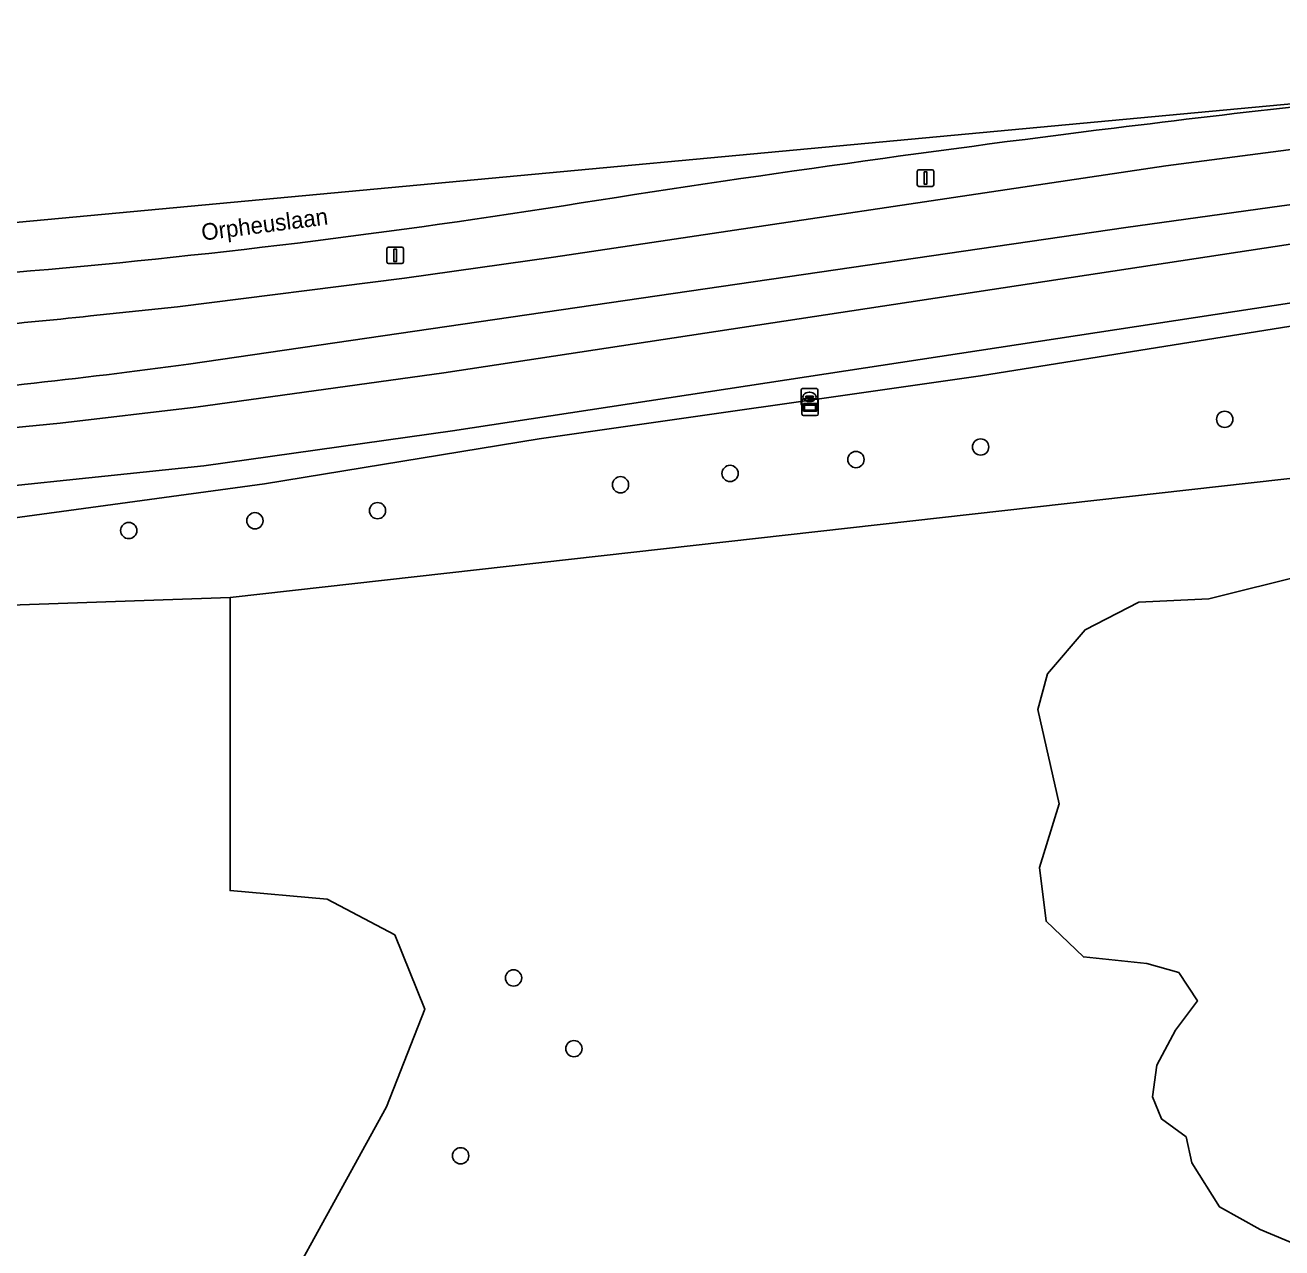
# Model space of a CAD drawing. Extents: x 161758 to 162722, y 384793 to 385405.
# Drawn here: x 162584.7 to 162660.3, y 385330.2 to 385403.7 of the extents above; entities that cross this region are included whole.
import ezdxf

# ---------------------------------------------------------------- set-up
doc = ezdxf.new("R2010")
doc.units = 0
for name, color, linetype in [('IMGEO_Berm_groen', 7, 'Continuous'), ('IMGEO_Boom', 7, 'Continuous'), ('IMGEO_Brandkraan', 7, 'Continuous'), ('IMGEO_Fietspad_gesloten', 7, 'Continuous'), ('IMGEO_Greppel_droge_sloot', 7, 'Continuous'), ('IMGEO_Groenvoorziening', 7, 'Continuous'), ('IMGEO_Lichtmast', 7, 'Continuous'), ('IMGEO_Loofbos', 7, 'Continuous'), ('IMGEO_Moeras', 7, 'Continuous'), ('IMGEO_Openbare_ruimte_label', 7, 'Continuous'), ('IMGEO_Rietland', 7, 'Continuous'), ('IMGEO_Rijbaan_lokaal_gesloten', 7, 'Continuous'), ('IMGEO_Verklikker', 7, 'Continuous')]:
    doc.layers.add(name, color=color, linetype=linetype)

msp = doc.modelspace()

# ---------------------------------------------------------------- linework, layer by layer
at = {"layer": 'IMGEO_Berm_groen'}
for points in [[(162660.257, 385392.853), (162650.874, 385391.567), (162594.54, 385383.334)], [(162576.692, 385378.812), (162586.817, 385379.801), (162594.968, 385380.749), (162609.882, 385382.816), (162660.767, 385390.553)]]:
    msp.add_lwpolyline(points, dxfattribs=at)
for centre, radius, start, end in [((162736.202, 384879.222), 519.215, 95.72988, 98.41074), ((162534.96, 385832.512), 453.112, 275.03456, 277.55569)]:
    msp.add_arc(centre, radius, start, end, dxfattribs=at)
at = {"layer": 'IMGEO_Boom'}
for centre in [(162656.822, 385380.027), (162642.149, 385378.364), (162634.653, 385377.609), (162627.089, 385376.773), (162620.501, 385376.091), (162605.894, 385374.536), (162590.941, 385373.343), (162598.524, 385373.928), (162614.071, 385346.448), (162617.699, 385342.198), (162610.889, 385335.757)]:
    msp.add_circle(centre, 0.489, dxfattribs=at)
at = {"layer": 'IMGEO_Brandkraan'}
for p, q in [((162631.361, 385380.945), (162631.361, 385381.797)), ((162631.436, 385381.871), (162632.288, 385381.871)), ((162631.62, 385381.365), (162631.62, 385381.377)), ((162632.058, 385381.328), (162631.66, 385381.328)), ((162631.663, 385381.414), (162632.061, 385381.414)), ((162631.849, 385381.651), (162631.874, 385381.651)), ((162632.104, 385381.377), (162632.104, 385381.365)), ((162632.362, 385381.797), (162632.362, 385380.945)), ((162632.288, 385380.871), (162631.436, 385380.871)), ((162631.872, 385381.091), (162631.847, 385381.091))]:
    msp.add_line(p, q, dxfattribs=at)
for points in [[(162631.361, 385380.945), (162631.361, 385381.797)], [(162631.436, 385381.871), (162632.288, 385381.871)], [(162632.362, 385381.797), (162632.362, 385380.945)], [(162632.288, 385380.871), (162631.436, 385380.871)]]:
    msp.add_lwpolyline(points, dxfattribs=at)
for centre, radius, start, end in [((162631.438, 385381.795), 0.0765, 91.55205, 178.44795), ((162631.438, 385381.795), 0.0765, 91.55205, 178.44795), ((162631.66, 385381.374), 0.0403, 85.87752, 175.75265), ((162631.657, 385381.364), 0.0366, 178.93798, 274.71019), ((162632.061, 385381.371), 0.043, 264.86636, 352.45326), ((162632.065, 385381.376), 0.0386, 1.73085, 96.63898), ((162632.286, 385381.795), 0.0765, 1.55205, 88.44795), ((162632.286, 385381.795), 0.0765, 1.55205, 88.44795), ((162631.438, 385380.947), 0.0765, 181.55205, 268.44795), ((162631.438, 385380.947), 0.0765, 181.55205, 268.44795), ((162632.286, 385380.947), 0.0765, 271.55205, 358.44795), ((162632.286, 385380.947), 0.0765, 271.55205, 358.44795)]:
    msp.add_arc(centre, radius, start, end, dxfattribs=at)
for centre, major_axis, ratio, start_param, end_param in [((162631.848, 385381.371), (-0.387, 0.002), 0.722429, 4.712389, 7.853982), ((162631.873, 385381.371), (-0.39, 0.002), 0.717154, 1.570796, 4.712389)]:
    msp.add_ellipse(centre, major_axis=major_axis, ratio=ratio, start_param=start_param, end_param=end_param, dxfattribs=at)
at = {"layer": 'IMGEO_Fietspad_gesloten'}
for points in [[(162677.197, 385393.316), (162660.767, 385390.553), (162609.882, 385382.816), (162594.968, 385380.749), (162586.817, 385379.801), (162576.692, 385378.812)], [(162576.625, 385375.27), (162595.45, 385377.228), (162610.41, 385379.329), (162660.98, 385387.042)]]:
    msp.add_lwpolyline(points, dxfattribs=at)
at = {"layer": 'IMGEO_Greppel_droge_sloot'}
msp.add_lwpolyline([(162588.634, 385386.239), (162593.869, 385386.792), (162607.514, 385388.514), (162616.475, 385389.77), (162653.281, 385395.256), (162662.034, 385396.405), (162671.163, 385397.596), (162683.886, 385399.101), (162688.344, 385399.628), (162699.463, 385400.722), (162707.521, 385401.494), (162711.775, 385401.902), (162711.608, 385403.721), (162673.311, 385400.161)], dxfattribs=at)
for centre, radius, start, end in [((162801.259, 384169.618), 1237.176, 95.936109, 97.014727), ((162773.539, 384402.583), 1002.57, 97.068339, 99.040149), ((162545.105, 385847.699), 460.49, 274.5738, 278.85735), ((162547.837, 385772.297), 388.208, 273.93158, 276.03232)]:
    msp.add_arc(centre, radius, start, end, dxfattribs=at)
at = {"layer": 'IMGEO_Groenvoorziening'}
for points in [[(162527.404, 385371.37), (162527.321, 385371.34), (162527.238, 385371.311), (162526.098, 385370.364), (162527.997, 385366.92), (162539.753, 385367.326), (162547.529, 385371.515), (162564.34, 385372.34), (162582.172, 385373.835), (162599.09, 385376.156), (162615.602, 385378.857), (162642.131, 385382.641), (162662.807, 385385.945), (162675.8, 385387.511), (162689.997, 385389.07), (162700.369, 385389.783), (162701.701, 385389.875)], [(162677.702, 385389.81), (162660.98, 385387.042), (162610.41, 385379.329), (162595.45, 385377.228), (162576.625, 385375.27)]]:
    msp.add_lwpolyline(points, dxfattribs=at)
at = {"layer": 'IMGEO_Lichtmast'}
for p, q in [((162638.337, 385394.131), (162638.337, 385394.931)), ((162638.337, 385394.931), (162638.337, 385394.131)), ((162638.437, 385395.031), (162639.227, 385395.031)), ((162639.227, 385395.031), (162638.437, 385395.031)), ((162639.327, 385394.931), (162639.327, 385394.131)), ((162639.327, 385394.131), (162639.327, 385394.931)), ((162639.227, 385394.031), (162638.437, 385394.031)), ((162638.437, 385394.031), (162639.227, 385394.031)), ((162606.556, 385390.384), (162607.346, 385390.384)), ((162607.346, 385390.384), (162606.556, 385390.384)), ((162606.456, 385389.484), (162606.456, 385390.284)), ((162606.456, 385390.284), (162606.456, 385389.484)), ((162607.446, 385390.284), (162607.446, 385389.484)), ((162607.446, 385389.484), (162607.446, 385390.284)), ((162607.346, 385389.384), (162606.556, 385389.384)), ((162606.556, 385389.384), (162607.346, 385389.384))]:
    msp.add_line(p, q, dxfattribs=at)
for points in [[(162638.757, 385394.906), (162638.907, 385394.906), (162638.907, 385394.156), (162638.757, 385394.156), (162638.757, 385394.906)], [(162606.876, 385390.259), (162607.026, 385390.259), (162607.026, 385389.509), (162606.876, 385389.509), (162606.876, 385390.259)]]:
    msp.add_lwpolyline(points, dxfattribs=at)
for centre, start, end in [((162638.437, 385394.931), 90, 180), ((162638.437, 385394.931), 90, 180), ((162639.227, 385394.931), 0, 90), ((162639.227, 385394.931), 360, 90), ((162638.437, 385394.131), 180, 270), ((162638.437, 385394.131), 180, 270), ((162639.227, 385394.131), 270, 0), ((162639.227, 385394.131), 270, 0), ((162606.556, 385390.284), 90, 180), ((162606.556, 385390.284), 90, 180), ((162607.346, 385390.284), 0, 90), ((162607.346, 385390.284), 360, 90), ((162606.556, 385389.484), 180, 270), ((162606.556, 385389.484), 180, 270), ((162607.346, 385389.484), 270, 0), ((162607.346, 385389.484), 270, 0)]:
    msp.add_arc(centre, 0.1, start, end, dxfattribs=at)
at = {"layer": 'IMGEO_Loofbos'}
msp.add_lwpolyline([(162663.808, 385382.469), (162662.807, 385385.945), (162642.131, 385382.641), (162615.602, 385378.857), (162599.09, 385376.156), (162582.172, 385373.835), (162564.34, 385372.34), (162547.529, 385371.515), (162539.753, 385367.326), (162563.714, 385368.155), (162597.028, 385369.308), (162671.437, 385377.676), (162671.166, 385383.084)], close=True, dxfattribs=at)
msp.add_lwpolyline([(162661.736, 385370.702), (162655.865, 385369.235), (162651.657, 385369.039), (162648.428, 385367.375), (162646.178, 385364.734), (162645.591, 385362.581), (162646.863, 385356.906), (162645.689, 385353.09), (162646.08, 385349.861), (162648.33, 385347.708), (162652.147, 385347.317), (162654.055, 385346.779), (162655.18, 385345.066), (162653.859, 385343.305), (162652.734, 385341.201), (162652.489, 385339.293), (162653.027, 385337.972), (162654.495, 385336.896), (162654.837, 385335.33), (162656.501, 385332.689), (162658.947, 385331.319), (162661.295, 385330.34)], dxfattribs=at)
at = {"layer": 'IMGEO_Moeras'}
for points in [[(162671.437, 385377.676), (162597.028, 385369.308), (162597.028, 385351.698), (162602.865, 385351.193), (162606.928, 385349.037), (162608.739, 385344.579), (162606.439, 385338.699), (162597.031, 385321.639)], [(162661.295, 385330.34), (162658.947, 385331.319), (162656.501, 385332.689), (162654.837, 385335.33), (162654.495, 385336.896), (162653.027, 385337.972), (162652.489, 385339.293), (162652.734, 385341.201), (162653.859, 385343.305), (162655.18, 385345.066), (162654.055, 385346.779), (162652.147, 385347.317), (162648.33, 385347.708), (162646.08, 385349.861), (162645.689, 385353.09), (162646.863, 385356.906), (162645.591, 385362.581), (162646.178, 385364.734), (162648.428, 385367.375), (162651.657, 385369.039), (162655.865, 385369.235), (162661.736, 385370.702)]]:
    msp.add_lwpolyline(points, dxfattribs=at)
at = {"layer": 'IMGEO_Rietland'}
msp.add_lwpolyline([(162584.226, 385320.452), (162586.967, 385320.788), (162590.202, 385320.219), (162593.971, 385320.048), (162597.031, 385321.639), (162606.439, 385338.699), (162608.739, 385344.579), (162606.928, 385349.037), (162602.865, 385351.193), (162597.028, 385351.698), (162597.028, 385369.308), (162563.714, 385368.155)], dxfattribs=at)
at = {"layer": 'IMGEO_Rijbaan_lokaal_gesloten'}
for points in [[(162673.311, 385400.161), (162572.041, 385390.745), (162531.225, 385390.164)], [(162684.364, 385395.843), (162683.886, 385399.101), (162671.163, 385397.596), (162662.034, 385396.405), (162653.281, 385395.256), (162616.475, 385389.77), (162607.514, 385388.514), (162593.869, 385386.792), (162588.634, 385386.239)], [(162650.874, 385391.567), (162660.257, 385392.853)], [(162594.54, 385383.334), (162650.874, 385391.567)]]:
    msp.add_lwpolyline(points, dxfattribs=at)
for centre, radius, start, end in [((162801.259, 384169.618), 1237.176, 95.936109, 97.014727), ((162773.539, 384402.583), 1002.57, 97.068339, 99.040149), ((162736.202, 384879.222), 519.215, 95.72988, 98.41074), ((162545.105, 385847.699), 460.49, 274.5738, 278.85735), ((162547.837, 385772.297), 388.208, 273.93158, 276.03232), ((162534.96, 385832.512), 453.112, 275.03456, 277.55569)]:
    msp.add_arc(centre, radius, start, end, dxfattribs=at)
at = {"layer": 'IMGEO_Verklikker'}
for p, q in [((162631.402, 385380.35), (162631.402, 385381.15)), ((162631.402, 385381.15), (162631.402, 385380.35)), ((162631.502, 385381.25), (162632.292, 385381.25)), ((162632.292, 385381.25), (162631.502, 385381.25)), ((162632.392, 385381.15), (162632.392, 385380.35)), ((162632.392, 385380.35), (162632.392, 385381.15)), ((162632.292, 385380.25), (162631.502, 385380.25)), ((162631.502, 385380.25), (162632.292, 385380.25))]:
    msp.add_line(p, q, dxfattribs=at)
for points in [[(162631.503, 385380.982), (162632.291, 385380.982), (162632.291, 385380.518), (162631.503, 385380.518), (162631.503, 385380.982)], [(162631.568, 385380.917), (162631.568, 385380.583), (162632.226, 385380.583), (162632.226, 385380.917), (162631.568, 385380.917)]]:
    msp.add_lwpolyline(points, dxfattribs=at)
for centre, start, end in [((162631.502, 385381.15), 90, 180), ((162631.502, 385381.15), 90, 180), ((162632.292, 385381.15), 0, 90), ((162632.292, 385381.15), 360, 90), ((162631.502, 385380.35), 180, 270), ((162631.502, 385380.35), 180, 270), ((162632.292, 385380.35), 270, 0), ((162632.292, 385380.35), 270, 0)]:
    msp.add_arc(centre, 0.1, start, end, dxfattribs=at)

# ---------------------------------------------------------------- texts
at = {"layer": 'IMGEO_Openbare_ruimte_label'}
msp.add_text('Orpheuslaan', height=1, rotation=7.35238, dxfattribs=at).set_placement((162595.37, 385390.764))

doc.saveas('drawing.dxf')
